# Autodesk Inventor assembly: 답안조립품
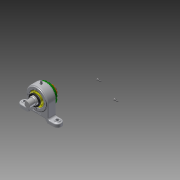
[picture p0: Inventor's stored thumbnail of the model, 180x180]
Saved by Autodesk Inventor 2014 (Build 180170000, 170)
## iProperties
Created: 2019-05
Part Number: 답안조립품
Document SubType Name: Assembly
Designer: kh
Author: kh
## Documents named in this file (13)
- C:\Users\kh\Desktop\490504V1009\답안조립품.iam
- C:\Users\kh\Desktop\490504V1009\본체.ipt
- C:\Users\kh\Desktop\490504V1009\개스킷.ipt
- C:\Users\kh\Desktop\490504V1009\그리스니플 M6.ipt
- 그리스니플  M6.ipt
- C:\Users\kh\Desktop\490504V1009\그리스니플개스킷.ipt
- C:\Users\kh\Desktop\490504V1009\베어링너트.ipt
- C:\Users\kh\Desktop\490504V1009\볼트 M4.ipt
- C:\Users\kh\Desktop\490504V1009\앵귤러 볼 베어링 7205.ipt
- C:\Users\kh\Desktop\490504V1009\오일 실 28 40 5 B.ipt
- C:\Users\kh\Desktop\490504V1009\축.ipt
- C:\Users\kh\Desktop\490504V1009\칼라.ipt
- C:\Users\kh\Desktop\490504V1009\커버.ipt
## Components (4 placed, 3 different names)
1. 개스킷:1 — Insert:10, Mate:2
2. 그리스니플  M6:1 — Insert:11, Angle:1
3. 그리스니플개스킷:1 — Insert:11, Insert:12
4. 개스킷:2 — Insert:9, Mate:1, Insert:13
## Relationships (8: Insert 5, Mate 2, Angle 1)
- Insert:9: 개스킷:2
- Mate:1: 개스킷:2
- Insert:10: 개스킷:1
- Mate:2: 개스킷:1
- Insert:11: 그리스니플  M6:1 ↔ 그리스니플개스킷:1
- Insert:12: 그리스니플개스킷:1
- Angle:1: 그리스니플  M6:1
- Insert:13: 개스킷:2
